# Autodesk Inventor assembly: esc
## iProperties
Shininess: 64.0
Length Units: 11269
Angle Units: 11279
Time Units: 11290
Mass Units: 11283
Length Display Precision: 3
Angle Display Precision: 2
Compacted: True
Created: 2004-07
Part Number: esc
Document SubType Name: Assembly
Designer: Peter
Manufacturer: Standard
Standards Organization: Custom
Density: 0.0
Volumn: 0.0
Area: 0.0
PropertySet Name: Model Information
Control State: 0
Master: False
Checked Out: False
Author: Peter
